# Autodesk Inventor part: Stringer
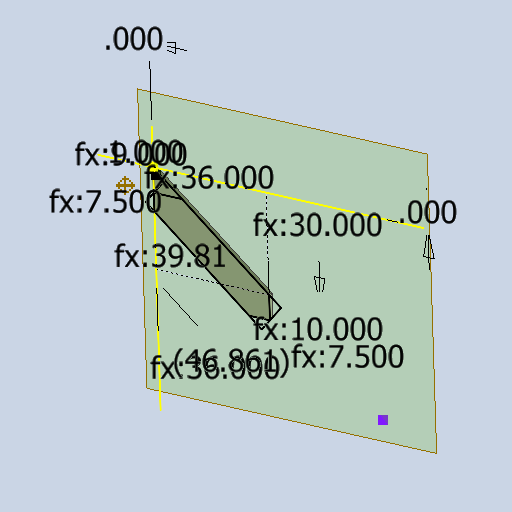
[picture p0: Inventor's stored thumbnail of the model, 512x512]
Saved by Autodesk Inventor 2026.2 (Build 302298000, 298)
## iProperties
Created: 2022-06
Part Number: Stringer
Material: Steel, Galvanized
Document SubType Name: Modeling
Designer: reaumed
Density: 7.85 g/cm^3
Appearance: Galvanized
Mass: 28099.6 g
Surface Area: 11501.7 cm^2
Volume: 3579.57 cm^3
Author: reaumed
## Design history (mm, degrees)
node "Half the Width Workplane"
sketch "Stringer Profile Sketch"
  geometry: L1 (0, 0)-(-914.4, 0); L2 (-914.4, 0)-(-914.4, -762); L3 (-914.4, -762)-(0, -762); L4 (0, -762)-(0, 0); L5 (-845.482, -1035.202)-(68.918, -273.202); L6 (68.918, -273.202)-(-93.689, -78.074); L7 (-93.689, -78.074)-(-1008.089, -840.074); L8 (-1008.089, -840.074)-(-845.482, -1035.202); L9 (0, -190.5)-(-228.6, -190.5); L10 (0, -190.5)-(0, -330.634); L11 (-746.239, -952.5)-(-914.4, -952.5); L12 (-914.4, -952.5)-(-914.4, -762); L13 (0, -1812.658)-(0, 302.11) reference; L14 (-2188.973, 0)-(445.234, 0) reference; L15 (0, -190.5)-(0, -54.23); L16 (-93.689, -78.074)-(-41.661, -34.717); A1 r 25.4 centre (-25.4, -54.23) between (0, -54.23) and (-41.661, -34.717); 8 further points
  constraints: 28 end point, 9 point on line, 4 parallel, 3 horizontal, 2 collinear, 2 perpendicular, 2 point on circle, 2 tangent, 2 vertical, 1 centre point
  dimensions: "d152" = 762 distance of L1.end L2.end (derived); "d153" = 914.4 distance of L2.end L3.end (derived); "d155" = 254 distance of L7.end L5.start (derived); "d156" = 1190.28205 distance of L6.end L7.end (derived); "d157" = 39.8056 deg angle of L3 L5 (derived); "d158" = 228.6 distance of L9.start L9.end (derived); "d159" = 190.5 distance of L11.end L12.end (derived); "d160" = 190.5 distance between parallel lines of L1 L9 (derived); "d161" = 914.4 distance between parallel lines of L12 L10 (derived); "d162" = 0 distance between parallel lines of L4 L13; "d163" = 0 distance between parallel lines of L1 L14; "d190" = 25.4 radius of A1 (derived)
extrude "Stringer Extrusion" new body sketch "Stringer Profile Sketch" distance "d164" = 38.1 (derived); taper "d165" = 0 deg
shell "Shell1" dims "d189" = 6.35 (derived)
body "Solid2"
other parameters: "StringerSpacing" = 342.9 (derived), "StringerWallThickness" = 6.35 [user parameter]
